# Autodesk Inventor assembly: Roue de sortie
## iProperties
Shininess: 64.0
Length Units: 11269
Angle Units: 11279
Time Units: 11290
Mass Units: 11283
Length Display Precision: 3
Angle Display Precision: 2
Compacted: True
Created: 2003-05
Part Number: Roue de sortie
Document SubType Name: Assembly
Designer: Philippe
Density: 0.0
Volumn: 0.0
Area: 0.0
PropertySet Name: Model Information
Control State: 0
Master: False
Checked Out: False
Author: Philippe
